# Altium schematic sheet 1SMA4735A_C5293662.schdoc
size 127 x 101 mm
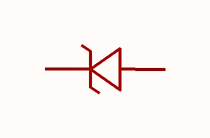
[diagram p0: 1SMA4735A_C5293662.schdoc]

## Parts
D?  1sma4735a_c5293662  [SMAG_L4.3-W2.6-LS5.3-RD]  (value not drawn)

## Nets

Not connected (* = marked no-connect by the designer): D? 1(C) 2(A)

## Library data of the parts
D? = 1sma4735a_c5293662: 二极管配置:1个独立式;稳压值(标称值):6.2V;稳压值(范围):-;耗散功率(Pd):1W;; Manufacturer: CJ(江苏长电/长晶); AddInBom: yes; ModelId: 3cd8680d946b497db8ea5837610a9736; ModelTransform: 208.661,102.362,0,0,0,0,0,0,0; Diode Configuration: 1个独立式; Zener Voltage(Nom): 6.2V; Reverse Leakage Current (Ir): 10uA@3V; Pd - Power Dissipation: 1W; Impedance(Zzt): 2Ω; Impedance(Zzk): 700Ω; Operating Junction Temperature Range: -55℃~+150℃; Tolerance: ±5%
